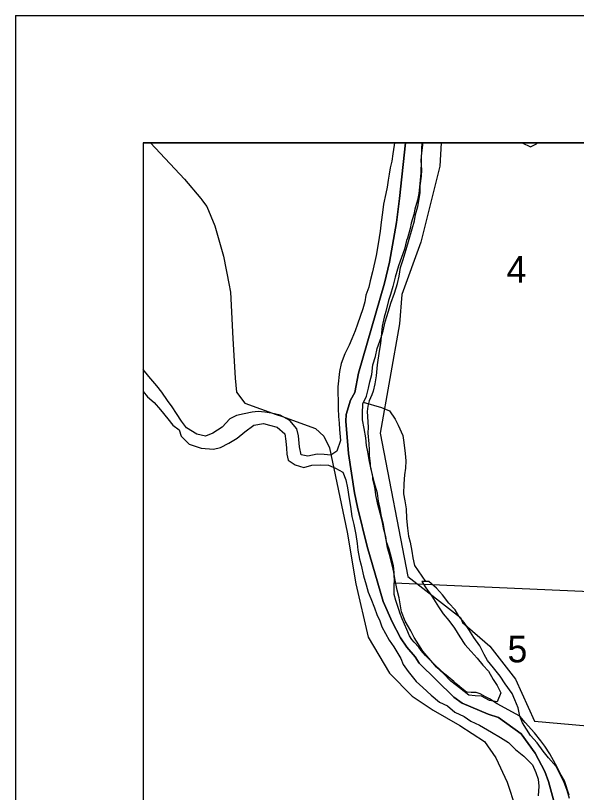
# Model space of a CAD drawing. Extents: x 0 to 42.5, y 0 to 22.
# Drawn here: x 2 to 2.44, y 20.39 to 21 of the extents above; entities that cross this region are included whole.
import ezdxf

# ---------------------------------------------------------------- set-up
doc = ezdxf.new("R2010")
doc.units = 0
for name, color, linetype in [('Default', 7, 'Continuous'), ('GM_X_Interchange_Ramps', 7, 'Continuous'), ('GM_X_Major_River', 7, 'Continuous'), ('GM_X_Minor_Lake', 7, 'Continuous'), ('GM_X_Minor_River', 7, 'Continuous'), ('GM_X_Section', 7, 'Continuous'), ('GM_X_Section_Text', 7, 'Continuous'), ('GM_X_Township_Road', 7, 'Continuous'), ('GM_X_Unincorporated', 7, 'Continuous'), ('SH_Cut_Line', 7, 'Continuous'), ('SH_Data', 7, 'Continuous')]:
    doc.layers.add(name, color=color, linetype=linetype)

msp = doc.modelspace()

# ---------------------------------------------------------------- linework, layer by layer
at = {"layer": 'Default'}
msp.add_lwpolyline([(2.4897, 20.9), (2.33377, 20.9), (2.33281, 20.88167), (2.31797, 20.82213), (2.30301, 20.78102), (2.30101, 20.75819), (2.28585, 20.67222), (2.30771, 20.55974), (2.3489, 20.52756), (2.35049, 20.52381), (2.37193, 20.50517), (2.39216, 20.47928), (2.40687, 20.44623), (2.44819, 20.44262)], dxfattribs=at)
at = {"layer": 'GM_X_Interchange_Ramps'}
for points in [[(2.42177, 20.38441), (2.41807, 20.39887), (2.41509, 20.40668), (2.40759, 20.42118), (2.39651, 20.43645), (2.37877, 20.44911), (2.37064, 20.45163), (2.35023, 20.4605), (2.34363, 20.4651), (2.3165, 20.4917), (2.3135, 20.49685), (2.30691, 20.5043), (2.30203, 20.51155), (2.29529, 20.52414), (2.28818, 20.54015), (2.27575, 20.58337), (2.26817, 20.6142), (2.26577, 20.62543), (2.26103, 20.65644), (2.25891, 20.68173), (2.25932, 20.68704), (2.2628, 20.69805), (2.26606, 20.7043), (2.269, 20.71929), (2.28932, 20.78986), (2.2934, 20.80655), (2.2987, 20.8375), (2.30109, 20.85649), (2.3057, 20.9), (2.1, 20.9), (2.1, 20.30748)], [(3.50401, 20.9), (2.3057, 20.9), (2.30109, 20.85649), (2.2987, 20.8375), (2.2934, 20.80655), (2.28932, 20.78986), (2.269, 20.71929), (2.26606, 20.7043), (2.2628, 20.69805), (2.25932, 20.68704), (2.25891, 20.68173), (2.26103, 20.65644), (2.26577, 20.62543), (2.26817, 20.6142), (2.27575, 20.58337), (2.28818, 20.54015), (2.29529, 20.52414), (2.30203, 20.51155), (2.30691, 20.5043), (2.3135, 20.49685), (2.3165, 20.4917), (2.34363, 20.4651), (2.35023, 20.4605), (2.37064, 20.45163), (2.37877, 20.44911), (2.39651, 20.43645), (2.40759, 20.42118), (2.41509, 20.40668), (2.41807, 20.39887), (2.42177, 20.38441)]]:
    msp.add_lwpolyline(points, dxfattribs=at)
at = {"layer": 'GM_X_Major_River'}
for points in [[(2.29725, 20.9), (2.29688, 20.89817), (2.29589, 20.89153), (2.2951, 20.88564), (2.29374, 20.88052), (2.29295, 20.87558), (2.29216, 20.87083), (2.29137, 20.86533), (2.29039, 20.86039), (2.28864, 20.85204), (2.28784, 20.8454), (2.28666, 20.8378), (2.28586, 20.83078), (2.28507, 20.82584), (2.28408, 20.81919), (2.28271, 20.81179), (2.27998, 20.79889), (2.27823, 20.79187), (2.27706, 20.78674), (2.27475, 20.78049), (2.27396, 20.77536), (2.27241, 20.76986), (2.26817, 20.75772), (2.26643, 20.7526), (2.26374, 20.74635), (2.26163, 20.74123), (2.25818, 20.73441), (2.25529, 20.72683), (2.25393, 20.72076)], [(2.34422, 20.5193), (2.34854, 20.51243), (2.35229, 20.50633), (2.35719, 20.50098), (2.36208, 20.49581), (2.3666, 20.49027), (2.37092, 20.48549), (2.37449, 20.47901), (2.37768, 20.47424), (2.38048, 20.46852), (2.3776, 20.46132), (2.37173, 20.46249), (2.3655, 20.46595), (2.36039, 20.46618), (2.35546, 20.46678), (2.34811, 20.47234), (2.34132, 20.4777), (2.33567, 20.48363), (2.33001, 20.48861), (2.32569, 20.49377), (2.31929, 20.50122), (2.31629, 20.50618), (2.31253, 20.5119), (2.30991, 20.51724), (2.3056, 20.52468), (2.3028, 20.53211), (2.30189, 20.53687), (2.30079, 20.54315), (2.29931, 20.54905), (2.29747, 20.55818), (2.29655, 20.56313), (2.29563, 20.56788), (2.29322, 20.57702), (2.29174, 20.58235), (2.29064, 20.58844), (2.28954, 20.59415), (2.28844, 20.60062), (2.28696, 20.60652), (2.28605, 20.61318), (2.28476, 20.61889), (2.28385, 20.62516), (2.28162, 20.63297), (2.27867, 20.64515), (2.27738, 20.65143), (2.27628, 20.65771), (2.27536, 20.66266), (2.27464, 20.66855), (2.27336, 20.67597), (2.27207, 20.68282), (2.2721, 20.68776), (2.27234, 20.69517), (2.27522, 20.70143), (2.27677, 20.7075), (2.27794, 20.71262), (2.2793, 20.71831), (2.2801, 20.72591), (2.28242, 20.73255), (2.28359, 20.73881), (2.28668, 20.74734), (2.28841, 20.75246), (2.28997, 20.75967), (2.29249, 20.76802), (2.29442, 20.77428), (2.29712, 20.78205), (2.29944, 20.78964), (2.3008, 20.79552), (2.30198, 20.80217), (2.30391, 20.80862), (2.30623, 20.81639), (2.30875, 20.82455), (2.31107, 20.83251), (2.313, 20.83877), (2.31379, 20.8439), (2.31553, 20.85016), (2.31652, 20.85605), (2.3173, 20.86098), (2.31734, 20.86649), (2.31833, 20.8739), (2.31874, 20.87903), (2.31822, 20.88625), (2.31863, 20.89214), (2.31943, 20.89822), (2.31934, 20.9)], [(2.25393, 20.72076), (2.25271, 20.7086), (2.25287, 20.70347), (2.25303, 20.69815), (2.25299, 20.69169), (2.25333, 20.68541), (2.25368, 20.68009), (2.25403, 20.67515), (2.25492, 20.66659), (2.25203, 20.65805), (2.24727, 20.65504), (2.24216, 20.65565), (2.23648, 20.65568), (2.22927, 20.65421), (2.22397, 20.65519), (2.22268, 20.66166), (2.22178, 20.67022), (2.22049, 20.67555), (2.21523, 20.68224), (2.20748, 20.68628), (2.20067, 20.68784), (2.19556, 20.68882), (2.19026, 20.68924), (2.18552, 20.6887), (2.17926, 20.68741), (2.17319, 20.68612), (2.16805, 20.68349), (2.16195, 20.67688), (2.15472, 20.67217), (2.14902, 20.66993), (2.14221, 20.67149), (2.13409, 20.67648), (2.13015, 20.68164), (2.12621, 20.68775), (2.12283, 20.6929), (2.11926, 20.69786), (2.11475, 20.70435), (2.1108, 20.70951), (2.10459, 20.71677), (2.1, 20.72212)], [(2.1, 20.70504), (2.10355, 20.70081), (2.10864, 20.69641), (2.11372, 20.69049), (2.11955, 20.68342), (2.12331, 20.67845), (2.1284, 20.67481), (2.12986, 20.66987), (2.13618, 20.66356), (2.14565, 20.66041), (2.15512, 20.65961), (2.16072, 20.66092), (2.16737, 20.66449), (2.17384, 20.66844), (2.17993, 20.67334), (2.18697, 20.67843), (2.19437, 20.6799), (2.19929, 20.67854), (2.20515, 20.67698), (2.21118, 20.67181), (2.21191, 20.6661), (2.21244, 20.66059), (2.21279, 20.65583), (2.21371, 20.65108), (2.21937, 20.64743), (2.22599, 20.6453), (2.23245, 20.64716), (2.23889, 20.6475), (2.24533, 20.64726), (2.25081, 20.64476), (2.25667, 20.64168), (2.2589, 20.63558), (2.26038, 20.6293), (2.26166, 20.62074), (2.26276, 20.61485), (2.26384, 20.60686), (2.26532, 20.60058), (2.26679, 20.59278), (2.26789, 20.58574), (2.26842, 20.58041), (2.2697, 20.57337), (2.271, 20.56861), (2.27285, 20.56024), (2.27489, 20.55319), (2.27656, 20.54748), (2.27861, 20.54253), (2.28141, 20.5351), (2.28327, 20.52996), (2.28571, 20.525), (2.28738, 20.52024), (2.29301, 20.50994), (2.29657, 20.50459), (2.3022, 20.49544), (2.30407, 20.49067), (2.30783, 20.48533), (2.31422, 20.4775), (2.3195, 20.47271), (2.3259, 20.46678), (2.3325, 20.46122), (2.33874, 20.45833), (2.34458, 20.45335), (2.35176, 20.44989), (2.35704, 20.44624), (2.36385, 20.44316), (2.37329, 20.43759), (2.38027, 20.43355), (2.38669, 20.42952), (2.39215, 20.42397), (2.39856, 20.4188), (2.40553, 20.4121), (2.40815, 20.40601), (2.40982, 20.40067), (2.41036, 20.39516), (2.40975, 20.38775)], [(2.43455, 20.38569), (2.43251, 20.39179), (2.4299, 20.39883), (2.42747, 20.40398), (2.42391, 20.41066), (2.41788, 20.41754), (2.41375, 20.42269), (2.40905, 20.42919), (2.40397, 20.43492), (2.39759, 20.44484), (2.39553, 20.45018), (2.39425, 20.45665), (2.39144, 20.46313), (2.38939, 20.46808), (2.38394, 20.47553), (2.38, 20.48163), (2.37473, 20.48813), (2.37022, 20.49386), (2.3674, 20.49863), (2.36403, 20.5053), (2.35953, 20.51198), (2.3554, 20.51828), (2.35183, 20.52362), (2.34769, 20.52859), (2.34469, 20.53355), (2.33979, 20.53891), (2.33472, 20.5454), (2.33001, 20.55075), (2.32417, 20.55592), (2.31867, 20.55576), (2.32186, 20.5508), (2.32637, 20.54431), (2.33163, 20.53611), (2.33538, 20.53038), (2.33971, 20.52522), (2.34422, 20.5193)]]:
    msp.add_lwpolyline(points, dxfattribs=at)
at = {"layer": 'GM_X_Minor_Lake'}
msp.add_lwpolyline([(2.39731, 20.9), (2.39731, 20.9), (2.40393, 20.89691), (2.40868, 20.89935), (2.409, 20.9)], dxfattribs=at)
at = {"layer": 'GM_X_Minor_River'}
msp.add_lwpolyline([(2.27267, 20.69669), (2.28691, 20.69242), (2.29334, 20.68991), (2.29766, 20.68323), (2.30009, 20.67846), (2.30383, 20.67046), (2.30456, 20.66494), (2.30545, 20.65638), (2.30598, 20.65049), (2.30595, 20.64479), (2.30516, 20.63947), (2.30455, 20.63263), (2.30431, 20.62465), (2.30542, 20.61913), (2.30632, 20.61286), (2.30666, 20.60525), (2.30737, 20.59784), (2.30809, 20.59156), (2.30958, 20.58661), (2.31067, 20.57976), (2.31159, 20.57443), (2.31288, 20.56853), (2.32139, 20.55595)], dxfattribs=at)
at = {"layer": 'GM_X_Section'}
msp.add_lwpolyline([(2.43414, 20.38808), (2.43041, 20.39947), (2.42797, 20.40383), (2.42347, 20.41257), (2.41896, 20.42054), (2.41501, 20.42662), (2.412, 20.4308), (2.40692, 20.43708), (2.39957, 20.44526), (2.39543, 20.4502), (2.37767, 20.45995), (2.37182, 20.46376), (2.36861, 20.46548), (2.36445, 20.46777), (2.36123, 20.46874), (2.35726, 20.46876), (2.35423, 20.46915), (2.35234, 20.47011), (2.34988, 20.47182), (2.3463, 20.47506), (2.34366, 20.47735), (2.3363, 20.48344), (2.32933, 20.48991), (2.32537, 20.49391), (2.3216, 20.4979), (2.31821, 20.50171), (2.31633, 20.50437), (2.31256, 20.50817), (2.31068, 20.51027), (2.30898, 20.51331), (2.30674, 20.51824), (2.30317, 20.52659), (2.3013, 20.53115), (2.30075, 20.53323), (2.29813, 20.54101), (2.29702, 20.54556), (2.29684, 20.55473), (2.45631, 20.54783)], dxfattribs=at)
at = {"layer": 'GM_X_Township_Road'}
for points in [[(2.10579, 20.9), (2.13258, 20.87158), (2.14531, 20.85642), (2.14616, 20.85527)], [(2.14616, 20.85527), (2.14828, 20.8524), (2.14998, 20.8501), (2.15626, 20.83502), (2.1632, 20.81119), (2.16751, 20.78839)], [(2.16751, 20.78839), (2.1683, 20.78425), (2.16857, 20.78283), (2.17043, 20.74653), (2.17235, 20.71536), (2.17336, 20.70433), (2.17972, 20.69589), (2.20448, 20.68696)], [(2.20448, 20.68696), (2.20849, 20.68551), (2.23526, 20.67586), (2.24165, 20.66989), (2.24628, 20.66072), (2.26014, 20.59446), (2.26688, 20.55411), (2.27666, 20.51221), (2.29321, 20.4839), (2.31103, 20.46584), (2.32741, 20.45481), (2.34833, 20.44279), (2.36773, 20.43021), (2.37669, 20.41738), (2.38558, 20.39847), (2.392, 20.37864), (2.3929, 20.35849), (2.39245, 20.33552), (2.39582, 20.31439), (2.40691, 20.29475), (2.41441, 20.27899)]]:
    msp.add_lwpolyline(points, dxfattribs=at)
at = {"layer": 'GM_X_Unincorporated'}
msp.add_lwpolyline([(2.48417, 20.9), (2.31851, 20.9), (2.31839, 20.89547), (2.31792, 20.87653), (2.31732, 20.87085), (2.31633, 20.86025), (2.31536, 20.85514), (2.31324, 20.84795), (2.31246, 20.84379), (2.31035, 20.83717), (2.30957, 20.83282), (2.30745, 20.82526), (2.30668, 20.82356), (2.30494, 20.81656), (2.30264, 20.81013), (2.30034, 20.80351), (2.29764, 20.79462), (2.2959, 20.78724), (2.29417, 20.781), (2.29244, 20.77627), (2.29032, 20.76776), (2.28897, 20.76341), (2.28761, 20.75622), (2.28622, 20.74259), (2.28524, 20.73672), (2.28368, 20.72594), (2.28269, 20.71723), (2.28171, 20.71098), (2.28036, 20.70512), (2.2794, 20.70247), (2.27729, 20.69755), (2.27632, 20.69358), (2.27574, 20.68923), (2.27644, 20.6771), (2.27622, 20.67237), (2.27694, 20.66384), (2.2773, 20.6593), (2.27727, 20.65456), (2.27819, 20.6485), (2.27799, 20.6466), (2.27985, 20.63826), (2.28003, 20.63636), (2.28059, 20.63409), (2.28114, 20.63087), (2.28169, 20.6284), (2.28224, 20.62385), (2.28354, 20.6176), (2.28558, 20.60982), (2.28763, 20.60224), (2.28818, 20.59788), (2.29004, 20.59124), (2.29078, 20.58726), (2.29283, 20.58138), (2.29469, 20.57474), (2.29618, 20.5683), (2.29672, 20.56261), (2.29684, 20.55473), (2.45631, 20.54783)], dxfattribs=at)
at = {"layer": 'SH_Cut_Line'}
msp.add_lwpolyline([(5.48884, 19.405), (5.50057, 19.55251), (5.51061, 19.66936), (5.5156, 19.73605), (5.52526, 19.85376), (5.53536, 19.98472), (5.54606, 20.11658), (5.56474, 20.34561), (5.56563, 20.35496), (5.56586, 20.35729), (5.60252, 20.8068), (5.60957, 20.9), (2.1, 20.9), (2.1, 16.00757)], dxfattribs=at)
at = {"layer": 'SH_Data'}
for p, q in [((2, 21), (9, 21)), ((2, 21), (2, 14)), ((2.1, 20.9), (2.1, 14.1)), ((2.1, 20.9), (8.9, 20.9))]:
    msp.add_line(p, q, dxfattribs=at)

# ---------------------------------------------------------------- texts
at = {"layer": 'GM_X_Section_Text'}
for s, p in [('4', (2.38516, 20.79043)), ('5', (2.38579, 20.49241))]:
    msp.add_text(s, height=0.02093, rotation=0.00001, dxfattribs=at).set_placement(p)

doc.saveas('drawing.dxf')
